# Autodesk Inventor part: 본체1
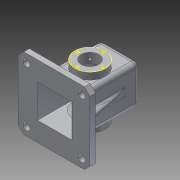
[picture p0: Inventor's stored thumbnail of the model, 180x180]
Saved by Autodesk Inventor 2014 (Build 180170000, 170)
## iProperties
Created: 2016-02
Part Number: 본체1
Material: Aluminum 6061
Document SubType Name: Modeling
Designer: user
Density: 2.71 g/cm^3
Appearance: Aluminum - Flat
Mass: 917.744 g
Surface Area: 1047.18 cm^2
Volume: 338.651 cm^3
Author: user
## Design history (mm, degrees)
sketch "Sketch1"
  geometry: L1 (-35, 55)-(35, 55); L2 (35, 55)-(35, -55); L3 (35, -55)-(-35, -55); L4 (-35, -55)-(-35, 55); L5 (35, -55)-(74.792, -55); L6 (74.792, -55)-(35, 45.791); 1 further point
  constraints: 12 end point, 2 parallel, 2 perpendicular, 1 horizontal, 1 point on line
  dimensions: "d44" = 111.544 deg angle of L5 L6
extrude "Extrusion1" new body sketch "Sketch1" stored distance "d4" = 70; taper "d5" = 0 deg
shell "Shell1" dims "d6" = 5
sketch "Sketch2"
  geometry: C1 r 27.5 at (0, 0); 1 further point
  constraints: 1 centre point, 1 coincident
  dimensions: "d7" = 55 diameter of C1
extrude "Extrusion2" join sketch "Sketch2" distance "d8" = 13; taper "d9" = 0 deg
sketch "Sketch3"
  geometry: 4 further points
hole "Hole1" sketch "Sketch3" at (0, 22.5), (-22.5, 0), (0, -22.5), (22.5, 0) diameter "d11" = 4; stored, may be unused: countersink angle "d15" = 82 deg, drill point angle "d17" = 118 deg; dims "d12" = 6, "d13" = 3.023, "d14" = 2, "d16" = 8
sketch "Sketch4"
  geometry: C1 r 2 at (0, -22.5) reference; C2 r 2 at (0, 22.5) reference; C3 r 2 at (-22.5, 0) reference; C4 r 2 at (22.5, 0) reference; C5 r 27.5 at (0, 0) reference
sketch "Sketch5"
  geometry: C1 r 27.5 at (0, 0) reference; C2 r 16 at (0, 0)
  constraints: 1 centre point, 1 coincident
  dimensions: "d18" = 32 diameter of C2
extrude "Extrusion3" cut sketch "Sketch5" stored distance "d19" = 13; taper "d20" = 0 deg
sketch "Sketch6"
  geometry: C1 r 16 at (30, -50) reference; C2 r 27.5 at (30, -52.5)
  constraints: 1 centre point
  dimensions: "d21" = 55 diameter of C2
extrude "Extrusion4" join sketch "Sketch6" distance "d22" = 7; taper "d23" = -45 deg
mirror "Mirror1"
sketch "Sketch7"
  geometry: L1 (65, -65)-(5, -65) reference; L2 (5, -65)-(5, -5) reference; L3 (5, -5)-(65, -5) reference; L4 (65, -5)-(65, -65) reference; L5 (-30, 30)-(100, 30); L6 (100, 30)-(100, -100); L7 (100, -100)-(-30, -100); L8 (-30, -100)-(-30, 30); 1 further point
  constraints: 8 end point, 2 parallel, 1 horizontal, 1 perpendicular
  dimensions: "d24" = 130 distance of L5.start L5.end; "d25" = 130 distance of L5.end L6.end; "d26" = 65 distance from line of L6 point (35, -35); "d27" = 65 distance from line of L5 point (35, -35)
extrude "Extrusion5" join sketch "Sketch7" distance "d28" = 10; taper "d29" = 0 deg
sketch "Sketch8"
  geometry: L1 (100, 100)-(-30, 100) reference; L2 (-15, 85)-(85, 85); L3 (85, 85)-(85, -15); L4 (85, -15)-(-15, -15); L5 (-15, -15)-(-15, 85); 1 further point
  constraints: 8 end point, 2 parallel, 1 horizontal, 1 perpendicular
  dimensions: "d30" = 100 distance of L2.start L2.end; "d31" = 100 distance of L2.end L3.end; "d32" = 15 horizontal distance of L1.start L2.end; "d33" = 15 distance from line of L1 L2.end
hole "Hole2" sketch "Sketch8" at (85, 85), (85, -15), (-15, -15), (-15, 85) diameter "d34" = 12; stored, may be unused: countersink angle "d38" = 82 deg, drill point angle "d40" = 118 deg; dims "d35" = 6, "d36" = 3.023, "d37" = 2, "d39" = 8
chamfer "Chamfer1" distance "d41" = 10; stored, may be unused: second distance "d42" = 2, angle "d43" = 45 deg
sketch "Sketch10"
  geometry: C1 r 20 at (35, 35); 1 further point
  constraints: 1 centre point, 1 coincident
  dimensions: "d51" = 40 diameter of C1
extrude "Extrusion7" join sketch "Sketch10" distance "d52" = 10; taper "d53" = 0 deg
sketch "Sketch11"
  geometry: C1 r 20 at (0, 0) reference
hole "Hole3" sketch "Sketch11" at (0, 0) diameter "d54" = 21; stored, may be unused: countersink angle "d58" = 82 deg, drill point angle "d60" = 118 deg; dims "d55" = 6, "d56" = 28, "d57" = 4, "d59" = 8
fillet "Fillet1" dims "d61" = 8
sketch "Sketch12"
  geometry: L1 (0, 0)-(-54, 0) reference; L2 (-32, 0)-(-22, 0); L3 (-22, 0)-(-22, 82.9); L4 (-22, 82.9)-(-32, 82.9); L5 (-32, 82.9)-(-32, 0); 1 further point
  constraints: 8 end point, 2 parallel, 1 horizontal, 1 perpendicular, 1 point on line
  dimensions: "d64" = 10 distance of L3.end L4.end; "d65" = 5 distance from line of L3 point (-27, 55)
extrude "Extrusion8" join sketch "Sketch12" distance "d66" = 15; taper "d67" = 0 deg
chamfer "Chamfer2" distance "d68" = 82; stored, may be unused: second distance "d69" = 15, angle "d70" = 80 deg
mirror "Mirror3"
chamfer "Chamfer3" distance "d71" = 15; stored, may be unused: second distance "d72" = 82, angle "d73" = 80 deg
fillet "Fillet4" dims "d74" = 3
fillet "Fillet5" dims "d75" = 3
fillet "Fillet6" dims "d76" = 3
sketch "Sketch13"
  geometry: L1 (-20.561, 39.864)-(23.303, 39.864); L2 (23.303, 39.864)-(23.303, 31.65); L3 (23.303, 31.65)-(-20.561, 31.65); L4 (-20.561, 31.65)-(-20.561, 39.864)
  constraints: 2 other
emboss "Emboss1" sketch "Sketch13" dims "d44" = 19.4681, "d78" = 0.5, "d79" = 0
body "Solid1"
